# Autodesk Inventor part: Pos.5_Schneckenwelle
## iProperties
Created: 2008-07
Part Number: Pos.5_Schneckenwelle
Document SubType Name: Modeling
Designer: nkrapf
Density: 1 g/cm^3
Author: nkrapf
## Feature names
1. Umdrehung1 [Revolution]
2. Extrusion1
3. Fase1 [Chamfer]
4. Fase2 [Chamfer]
